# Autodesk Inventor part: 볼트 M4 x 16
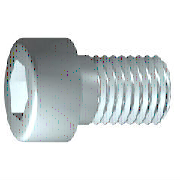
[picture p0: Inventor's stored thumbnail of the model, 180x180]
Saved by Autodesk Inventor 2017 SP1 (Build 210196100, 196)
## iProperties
Created: 2012-02
Part Number: 볼트 M4 x 16
Material: 스테인리스강
Description: 6각 소켓 머리 캡 나사
Document SubType Name: Modeling
Standard: ISO 4762
Designer: mduedu
Standard Revision: Fourth edition 2004-03-01
Standards Organization: ISO
Language: ko-KR
Size Designation: M4 x 16
Categories: <MemberInstance><Categories><Category DisplayName="조임쇠" InternalName="e4da775c-781d-43d5-af7c-5136215cf5a6" Mnemonic="FSTN"><Category DisplayName="볼트" InternalN
Density: 7.75 g/cm^3
Appearance: 반광택
IsCustomPart: 0
Author: mduedu
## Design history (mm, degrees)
sketch "스케치1"
  geometry: L1 (-1, 0)-(16, 0); L2 (16, 0)-(16, 2); L3 (16, 2)-(1.75, 2); L4 (1.75, 2)-(1.32, 2); L5 (1.32, 2)-(0, 2); L6 (0, 2)-(0, 3.5); L7 (0, 3.5)-(-4, 3.5); L8 (-4, 3.5)-(-4, 1.732); L9 (-4, 1.732)-(-2, 1.732); L10 (-2, 1.732)-(-1, 0); L11 (-8, 0)-(20, 0) reference; L12 (0, -0.7)-(0, 4.2) reference; L13 (1.75, 2)-(0, 2)
  constraints: 22 end point, 6 parallel, 2 collinear, 2 perpendicular, 1 horizontal, 1 point on line
  dimensions: "d1" = 14.25 distance from line of L3.end L2 (= GEL); "d2" = 0.42952 distance of L4.end L3.end (computed from GAL); "d3" = 4 distance between parallel lines of L8 L6 (= KOH); "d4" = 2 distance of L8.end L9.end (= INTI); "d5" = 60 deg angle of L10 L1; "d6" = 4 diameter of L3 L1 (= GD); "d7" = 4 diameter of L5 L1 (= BDM); "d8" = 3.4641 diameter of L9 L1 (= 1.1547 x SW); "d9" = 7 diameter of L7 L1 (= KOD); "d26" = 16 distance between parallel lines of L12 L2 (= NLG)
revolve "본체" sketch "스케치1" stored, may be unused: angle "d10" = 90 deg
sketch "스케치2"
  geometry: L1 (0, -4.9)-(0, 4.9) reference; L2 (-4.9, 0)-(4.9, 0) reference; L3 (1.732, 0)-(0.866, -1.5); L4 (0.866, -1.5)-(-0.866, -1.5); L5 (-0.866, -1.5)-(-1.732, 0); L6 (-1.732, 0)-(-0.866, 1.5); L7 (-0.866, 1.5)-(0.866, 1.5); L8 (0.866, 1.5)-(1.732, 0); 2 further points
  constraints: 12 end point, 1 coincident, 1 horizontal alignment, 1 point on line, 12 other
extrude "슬롯" join sketch "스케치2" stored distance "d11" = 10; taper "d12" = 0 deg
workplane "Work Plane1"
fillet "Fillet2" dims "d30" = 0.1 (= R)
body "Solid1"
fillet "모깎기1" dims "d17" = 0.4 (= RR)
feature "스레드" dims "d13" = 14.25 (= GEL), "d14" = 0
chamfer "모따기1" distance "d15" = 0.42941 (= -0.5 x SPD + 0.5 x GD); stored, may be unused: second distance "d16" = 0.42941 (= GUL), angle "d27" = 45 deg
other parameters: "GD" = 4 [user parameter; used in 2 equation terms], "NLG" = 16 [user parameter; used in 1 equation term], "GEL" = 14.25 [user parameter; used in 2 equation terms], "KOD" = 7 [user parameter; used in 1 equation term], "KOH" = 4 [user parameter; used in 1 equation term], "INTI" = 2 [user parameter; used in 1 equation term], "GAL" = 0.42941 (= 0.61345 x PTC) [user parameter; used in 1 equation term], "GUL" = 0.42941 (= 0.61345 x PTC) [user parameter; used in 1 equation term], "BDM" = 4 (= NND) [user parameter; used in 1 equation term], "SW" = 3 [user parameter; used in 2 equation terms], "RR" = 0.4 [user parameter; used in 1 equation term], "SPD" = 3.14117 (= NND - 1.2269 x PTC) [user parameter; used in 1 equation term], "d19" = 0, "d28" = 0, "d29" = 0, "R" = 0.1 [user parameter; used in 1 equation term], "TOA" = 30 deg [user parameter], "GD1" = 3.14117 (= THREADDIA - 1.2269 x PTC) [user parameter], "THREADDIA" = 4 [user parameter; used in 1 equation term], "FAWI" = 45 deg [user parameter], "TPU" = 14.28571 (computed from PTC) [user parameter], "PTC" = 0.7 [user parameter; used in 5 equation terms], "NND" = 4 [user parameter; used in 2 equation terms], "E0" = 3.465 (= 1.155 x SW) [user parameter]
